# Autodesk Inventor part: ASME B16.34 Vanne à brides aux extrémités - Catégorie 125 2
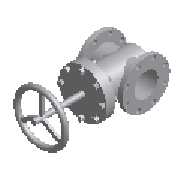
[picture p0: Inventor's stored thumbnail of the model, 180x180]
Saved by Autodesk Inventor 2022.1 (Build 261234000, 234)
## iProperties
Created: 2021-02
Part Number: ASME B16.34 Vanne à brides aux extrémités - Catégorie 125 2
Material: Fonte, moulé
Description: Vanne
Document SubType Name: Modeling
Standard: ASME B16.34
Designer: Fabian
Standards Organization: ANSI
Language: fr-FR
Size Designation: 2
Categories: <MemberInstance><Categories><Category DisplayName="Tubes et tuyaux" InternalName="4347fa0f-2144-441d-94cd-e3e15c92b736" Mnemonic="TUBEANDPIPE"><CategoryParamete
Density: 7.15 g/cm^3
Appearance: Fonte grise
NAME: PIPING: ASME B16.34 Gate Valve Flanged Ends - Class 125
DATA: <meta><inlinegroups number="1" deflen="25.4"></inlinegroups><connections number="2"></connections><angles><a>3.14159265358979</a></angles></meta>
IsCustomPart: 0
Author: Fabian
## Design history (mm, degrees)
sketch "Sketch1"
  geometry: L1 (0, 0)-(0, 76.2); L2 (0, 76.2)-(15.748, 76.2); L3 (15.748, 76.2)-(15.748, 33.274); L4 (15.748, 33.274)-(162.052, 33.274); L5 (88.9, 33.274)-(88.9, 0); L6 (177.8, 0)-(0, 0); L7 (177.8, 76.2)-(162.052, 76.2); L8 (177.8, 0)-(177.8, 76.2); L9 (162.052, 76.2)-(162.052, 33.274); 2 further points
  constraints: 18 end point, 6 symmetric about line, 2 coincident, 2 midpoint, 2 parallel, 1 vertical, 3 other
  dimensions: "d0" = 152.4 diameter of L2 L6 (= O); "d1" = 15.748 distance between parallel lines of L3 L1 (= C1); "d2" = 177.8 distance of L6.start L1.start (= A); "d3" = 66.548 diameter of L4 L6 (= d + 2 x t)
revolve "Revolution1" sketch "Sketch1" stored, may be unused: angle "d7" = 90 deg
sketch "Sketch2"
  geometry: L1 (0, 0)-(-42.656, 42.656); L2 (0, 0)-(-60.325, 0); C1 r 9.525 at (-42.656, 42.656); C2 r 76.2 at (0, 0) reference; A1 r 60.325 centre (0, 0) between (-42.656, 42.656) and (-60.325, 0)
  constraints: 4 end point, 2 centre point, 2 point on circle, 1 coincident, 1 concentric, 1 horizontal
  dimensions: "d4" = 120.65 diameter of A1 (= BC); "d5" = 19.05 diameter of C1 (= DH); "d42" = 45 deg angle of L1 L2 (computed from Nu)
extrude "Extrusion1" cut sketch "Sketch2" extent not by distance; taper "d6" = 0 deg; stored distance "d10" = 25.4
pattern_circular "Circular Pattern1" dims angle "d9" = 360 deg
sketch "Sketch3"
  geometry: L1 (-177.8, 76.2)-(-177.8, -76.2) reference; L2 (-177.8, 0)-(0, 0); L3 (-88.9, -59.03)-(-88.9, 307.975); L4 (-88.9, 307.975)-(-78.867, 307.975); L5 (-78.867, 307.975)-(-78.867, 282.892); L6 (-78.867, 287.909)-(11.43, 287.909); L7 (11.43, 267.843)-(-78.867, 267.843); L8 (-78.867, 272.859)-(-78.867, 131.318); L9 (-78.867, 131.318)-(-12.7, 131.318); L10 (-12.7, 131.318)-(-12.7, 99.822); L11 (-12.7, 99.822)-(-52.299, 99.822); L12 (-52.299, 99.822)-(-52.299, -33.274); L13 (-88.9, 0)-(-52.299, 0); L14 (11.43, 287.909)-(11.43, 267.843); L15 (-78.867, 282.892)-(-7.292, 282.892); L16 (1.397, 277.876)-(-88.9, 277.876); L17 (-78.867, 272.859)-(-7.292, 272.86); L18 (-15.748, -33.274)-(-162.052, -33.274) reference; L19 (0, 76.2)-(0, -76.2) reference; A1 r 10.033 centre (1.397, 277.876) between (-7.292, 272.86) and (-7.292, 282.892); A2 r 38.885 centre (-88.9, -20.145) between (-88.9, -59.03) and (-52.299, -33.274)
  constraints: 32 end point, 8 point on line, 6 parallel, 6 perpendicular, 5 point on circle, 3 midpoint, 3 tangent, 2 centre point, 2 symmetric about line, 1 collinear, 1 other
  dimensions: "d11" = 73.2028 diameter of L12 L3 (computed from t, d, x); "d12" = 152.4 diameter of L10 L3 (= O); "d14" = 31.496 distance between parallel lines of L11 L9 (= 2 x C1); "d15" = 99.822 distance between parallel lines of L13 L11 (= 0.5 x O + 1.5 x C1); "d16" = 200.66 diameter of L14 L3 (= D); "d17" = 277.876 distance from line of L2 L16.start (= H); "d18" = 10.033 radius of A1 (= 0.05 x D); "d19" = 20.066 distance between parallel lines of L6 L4 (= 0.1 x D); "d20" = 20.066 diameter of L5 L3 (= 0.1 x D); "d21" = 10.033 distance between parallel lines of L17 L15 (= 0.05 x D); "d41" = 25.7556 distance from line of L3.start L18 (= -0.6 x t + 0.3 x O - 0.3 x d)
revolve "Revolution2" sketch "Sketch3" stored, may be unused: angle "d24" = 90 deg
sketch "Sketch4"
  geometry: L1 (0, 0)-(0, 81.608); L2 (6.689, 7.478)-(6.689, 81.334); L3 (9.821, 2.053)-(73.781, -34.874); L4 (0, 0)-(70.675, -40.804); L5 (-9.821, 2.053)-(-73.781, -34.874); L6 (-6.689, 7.478)-(-6.689, 81.334); L7 (3.132, -9.532)-(67.093, -46.459); L8 (-3.132, -9.532)-(-67.093, -46.459); C1 r 81.608 at (0, 0) reference; C2 r 10.033 at (0, 0) reference; A1 r 81.608 centre (0, 0) between (73.781, -34.874) and (6.689, 81.334); A2 r 10.033 centre (0, 0) between (9.821, 2.053) and (6.689, 7.478); A3 r 81.608 centre (0, 0) between (-6.689, 81.334) and (-73.781, -34.874); A4 r 10.033 centre (0, 0) between (-6.689, 7.478) and (-9.821, 2.053); A5 r 81.608 centre (0, 0) between (-67.093, -46.459) and (67.093, -46.459); A6 r 10.033 centre (0, 0) between (-3.132, -9.532) and (3.132, -9.532); 4 further points
  constraints: 18 point on circle, 16 end point, 6 centre point, 6 concentric, 3 coincident, 2 parallel, 1 vertical, 37 other
  dimensions: "d22" = 120 deg angle of L3 L2; "d23" = 6.68867 distance between parallel lines of L1 L2 (= 0.0333333 x D); "d25" = 6.68867 distance between parallel lines of L4 L3 (= 0.0333333 x D); "d34" = 360 deg dimension on C1.centre L2.start (derived)
extrude "Extrusion2" cut sketch "Sketch4" taper "d27" = 0 deg; stored distance "d36" = 25.4
sketch "Sketch5"
  geometry: C1 r 76.2 at (0, 0) reference; C2 r 25.4 at (0, 0)
  constraints: 1 centre point, 1 coincident, 1 concentric
  dimensions: "d28" = 50.8 diameter of C2 (= d)
extrude "Extrusion3" cut sketch "Sketch5" extent not by distance; taper "d29" = 0 deg; stored distance "d39" = 25.4
workplane "Work Plane1"
sketch "Sketch6" dims "d30" = 120.65 (= BC), "d31" = 22.86 (= 1.2 x DH)
  geometry: L1 (0, 0)-(60.325, 0); L2 (66.04, -9.899)-(54.61, -9.899); L3 (54.61, -9.899)-(48.895, 0); L4 (48.895, 0)-(54.61, 9.899); L5 (54.61, 9.899)-(66.04, 9.899); L6 (66.04, 9.899)-(71.755, 0); L7 (71.755, 0)-(66.04, -9.899); C1 r 76.2 at (0, 0) reference; 2 further points
  constraints: 14 end point, 2 coincident, 1 horizontal, 1 horizontal alignment, 1 parallel, 17 other
extrude "Extrusion4" join sketch "Sketch6" distance "d35" = 55.118 (= 3.5 x C1); taper "d37" = 0 deg
pattern_circular "Circular Pattern2" dims angle "d40" = 360 deg
workaxis "Work Axis1"
workpoint "Work Point1"
workaxis "Work Axis2"
workpoint "Work Point2"
body "Solid1"
other parameters: "A" = 177.8 [user parameter; used in 1 equation term], "H" = 277.876 [user parameter; used in 1 equation term], "D" = 200.66 [user parameter; used in 7 equation terms], "d" = 50.8 [user parameter; used in 4 equation terms], "t" = 7.874 [user parameter; used in 3 equation terms], "O" = 152.4 [user parameter; used in 4 equation terms], "C1" = 15.748 [user parameter; used in 5 equation terms], "BC" = 120.65 [user parameter; used in 2 equation terms], "DH" = 19.05 [user parameter; used in 2 equation terms], "d32" = 11.811 (= 0.75 x C1), "x" = 11 [user parameter; used in 1 equation term]
